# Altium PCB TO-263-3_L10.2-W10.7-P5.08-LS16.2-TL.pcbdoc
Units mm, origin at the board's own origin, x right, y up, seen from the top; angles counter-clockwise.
Board outline 28.85 x 23.4 mm, 2 copper layers (Top Layer, Bottom Layer), stack 0 mm thick; 1 components, 0 nets, 3 pads, 0 vias.
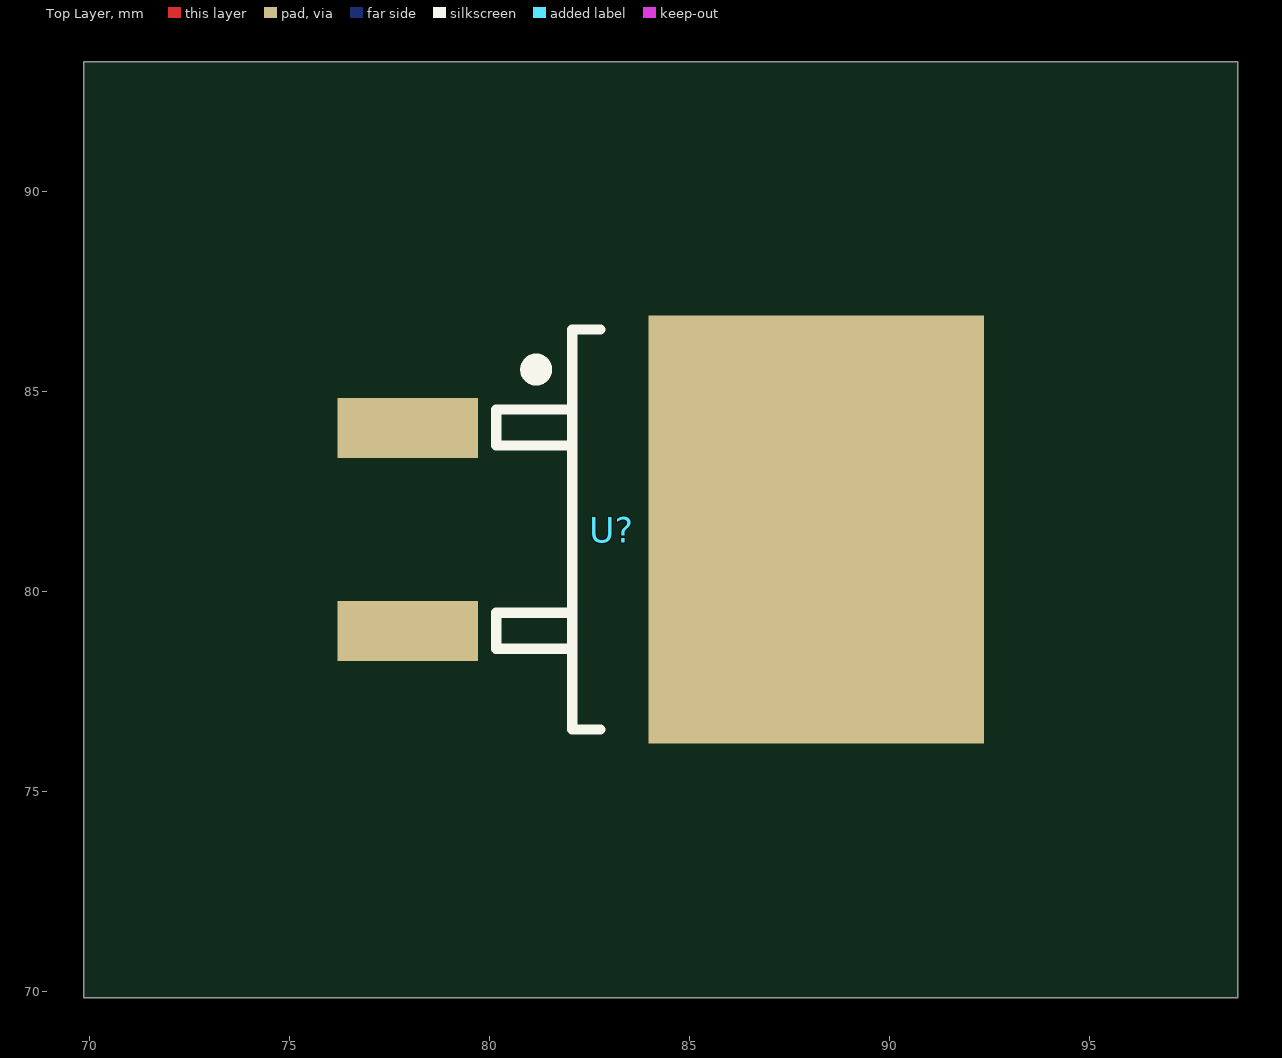
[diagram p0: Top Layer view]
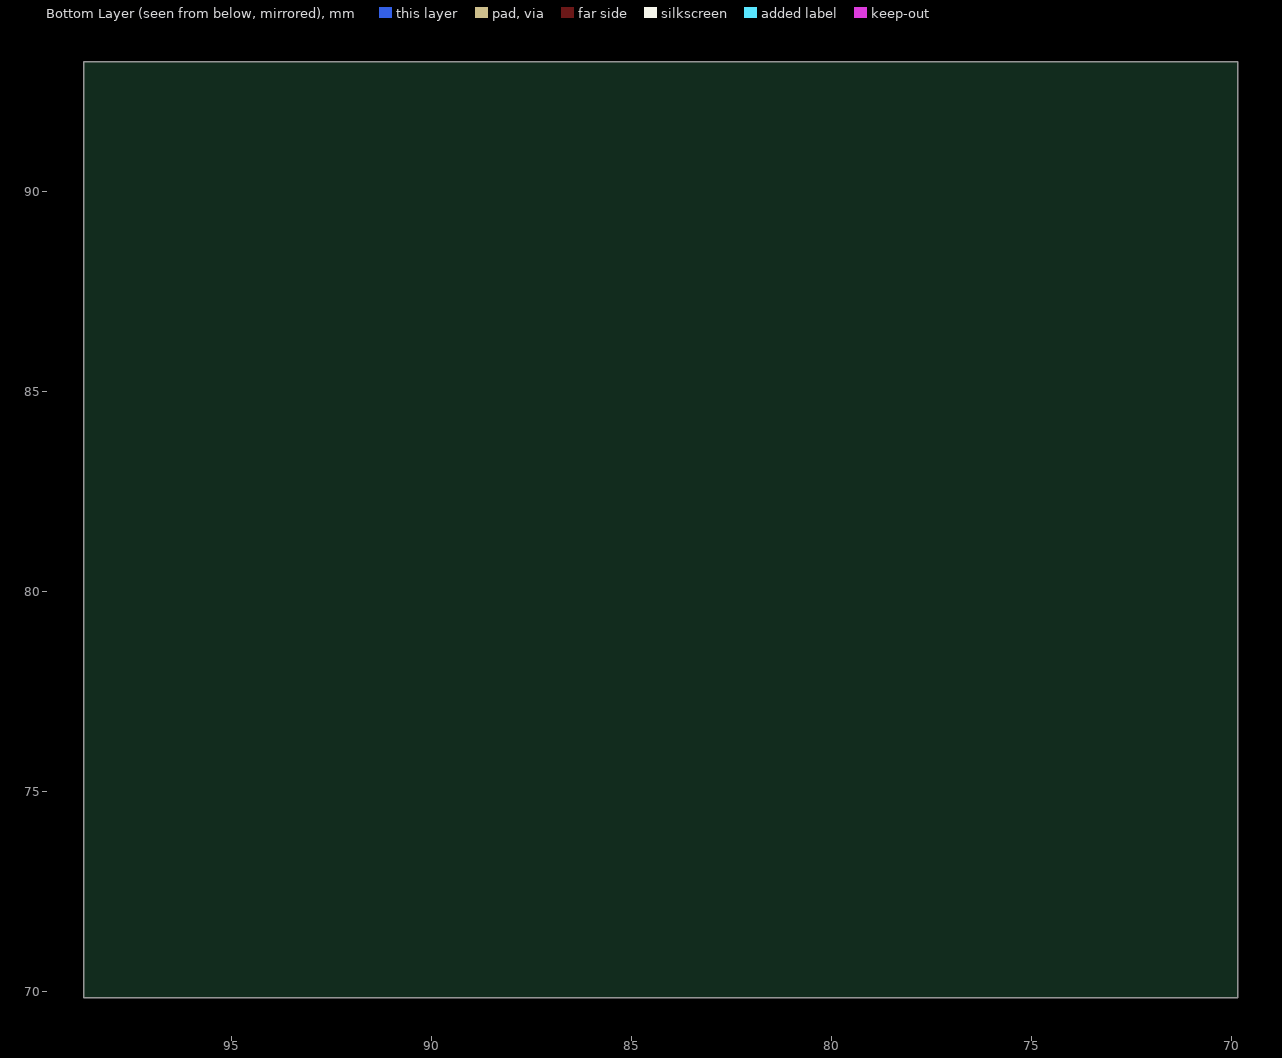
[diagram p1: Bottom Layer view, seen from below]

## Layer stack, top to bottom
Top Layer: signal copper (thickness not stored)
Bottom Layer: signal copper (thickness not stored)

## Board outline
98.705,69.85 69.85,69.85 69.85,93.25 98.705,93.25

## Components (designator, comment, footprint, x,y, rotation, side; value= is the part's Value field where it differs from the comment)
U? "" TO-263-3_L10.2-W10.7-P5.08-LS16.2-TL 83.058,81.55 r0 top

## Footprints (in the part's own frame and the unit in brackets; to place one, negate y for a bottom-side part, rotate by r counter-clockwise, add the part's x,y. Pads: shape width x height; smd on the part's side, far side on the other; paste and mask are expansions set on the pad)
TO-263-3_L10.2-W10.7-P5.08-LS16.2-TL [mm]
  rect 3.504x1.5 smd: 1(-5.106,2.54) 3(-5.106,-2.54)
  rect 8.38x10.7 smd: 2(5.106,0)
  silkscreen extent -2.89,-5 -0.29,5

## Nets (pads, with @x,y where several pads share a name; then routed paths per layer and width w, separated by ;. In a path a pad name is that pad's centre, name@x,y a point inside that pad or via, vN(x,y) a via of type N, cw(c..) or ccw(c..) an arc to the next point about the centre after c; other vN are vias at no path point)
pads on no net: U?.1 U?.2 U?.3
